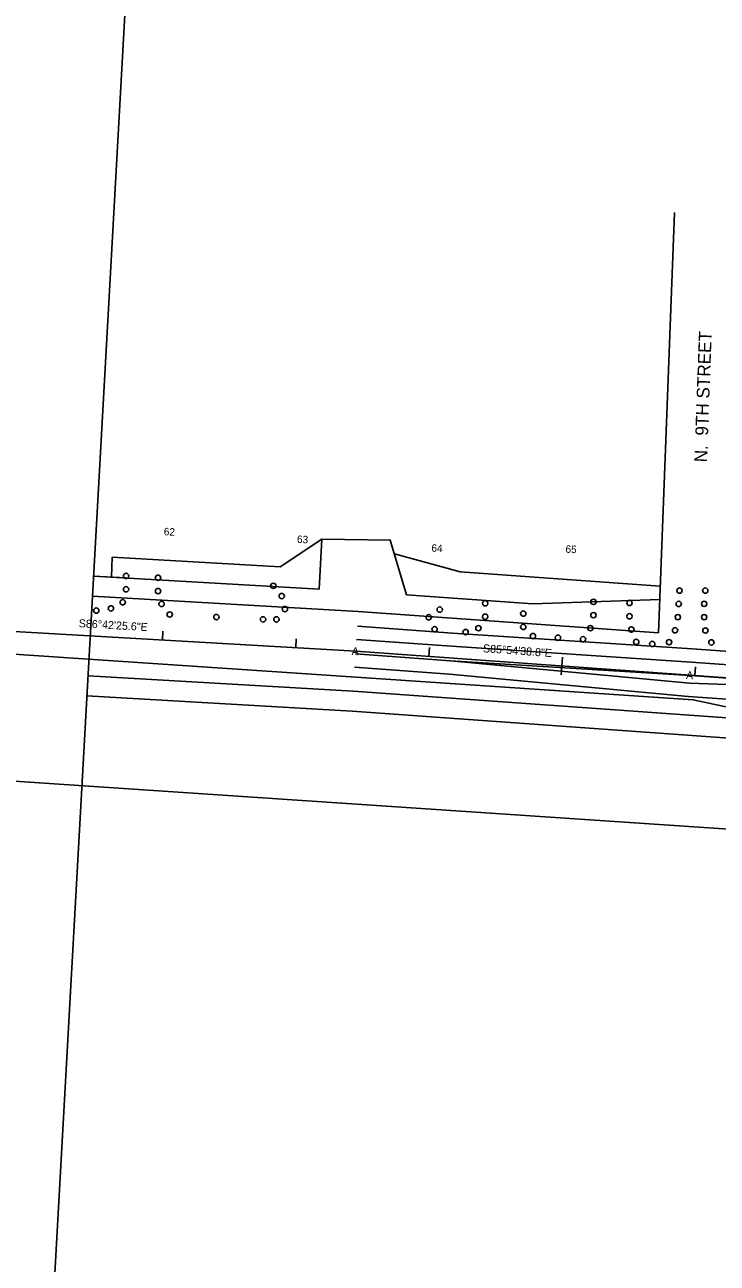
# Model space of a CAD drawing. Extents: x 679444 to 687671, y 733868 to 736107.
# Drawn here: x 685370 to 685889, y 734431 to 735359 of the extents above; entities that cross this region are included whole.
import ezdxf

# ---------------------------------------------------------------- set-up
doc = ezdxf.new("R2010")
doc.units = 0
for name, color, linetype in [('$', 7, 'Continuous'), ('BASE', 7, 'Continuous'), ('border All Plan 20-40 - Level 1', 7, 'Continuous'), ('Clipping Boundary', 7, 'Continuous'), ('MOT Stage 1', 7, 'Continuous'), ('MOT Stage 1 Lanes', 7, 'Continuous'), ('R_Horz Alg', 7, 'Continuous'), ('R_Horz Alg Station', 7, 'Continuous'), ('R_TYPE_A_CURB', 7, 'Continuous'), ('RW-EX', 7, 'Continuous'), ('RW-PR', 7, 'Continuous')]:
    doc.layers.add(name, color=color, linetype=linetype)

# ---------------------------------------------------------------- blocks, each defined once
blk = doc.blocks.new('BAREL_1772')
at = {"layer": 'MOT Stage 1'}
blk.add_circle((0, 0), 2.88, dxfattribs=at)
blk = doc.blocks.new('BAREL_1773')
at = {"layer": 'MOT Stage 1'}
blk.add_circle((0, 0), 2.88, dxfattribs=at)
blk = doc.blocks.new('BAREL_1774')
at = {"layer": 'MOT Stage 1'}
blk.add_circle((0, 0), 2.88, dxfattribs=at)
blk = doc.blocks.new('BAREL_1775')
at = {"layer": 'MOT Stage 1'}
blk.add_circle((0, 0), 2.88, dxfattribs=at)
blk = doc.blocks.new('BAREL_1776')
at = {"layer": 'MOT Stage 1'}
blk.add_circle((0, 0), 2.88, dxfattribs=at)
blk = doc.blocks.new('BAREL_1777')
at = {"layer": 'MOT Stage 1'}
blk.add_circle((0, 0), 2.88, dxfattribs=at)
blk = doc.blocks.new('BAREL_1778')
at = {"layer": 'MOT Stage 1'}
blk.add_circle((0, 0), 2.88, dxfattribs=at)
blk = doc.blocks.new('BAREL_1779')
at = {"layer": 'MOT Stage 1'}
blk.add_circle((0, 0), 2.88, dxfattribs=at)
blk = doc.blocks.new('BAREL_1790')
at = {"layer": 'MOT Stage 1'}
blk.add_circle((0, 0), 2.88, dxfattribs=at)
blk = doc.blocks.new('BAREL_1791')
at = {"layer": 'MOT Stage 1'}
blk.add_circle((0, 0), 2.88, dxfattribs=at)
blk = doc.blocks.new('BAREL_1792')
at = {"layer": 'MOT Stage 1'}
blk.add_circle((0, 0), 2.88, dxfattribs=at)
blk = doc.blocks.new('BAREL_1793')
at = {"layer": 'MOT Stage 1'}
blk.add_circle((0, 0), 2.88, dxfattribs=at)
blk = doc.blocks.new('BAREL_1794')
at = {"layer": 'MOT Stage 1'}
blk.add_circle((0, 0), 2.88, dxfattribs=at)
blk = doc.blocks.new('BAREL_1795')
at = {"layer": 'MOT Stage 1'}
blk.add_circle((0, 0), 2.88, dxfattribs=at)
blk = doc.blocks.new('BAREL_1807')
at = {"layer": 'MOT Stage 1'}
blk.add_circle((0, 0), 2.88, dxfattribs=at)
blk = doc.blocks.new('BAREL_1808')
at = {"layer": 'MOT Stage 1'}
blk.add_circle((0, 0), 2.88, dxfattribs=at)
blk = doc.blocks.new('BAREL_1809')
at = {"layer": 'MOT Stage 1'}
blk.add_circle((0, 0), 2.88, dxfattribs=at)
blk = doc.blocks.new('BAREL_1810')
at = {"layer": 'MOT Stage 1'}
blk.add_circle((0, 0), 2.88, dxfattribs=at)
blk = doc.blocks.new('BAREL_1811')
at = {"layer": 'MOT Stage 1'}
blk.add_circle((0, 0), 2.88, dxfattribs=at)
blk = doc.blocks.new('BAREL_1812')
at = {"layer": 'MOT Stage 1'}
blk.add_circle((0, 0), 2.88, dxfattribs=at)
blk = doc.blocks.new('BAREL_1813')
at = {"layer": 'MOT Stage 1'}
blk.add_circle((0, 0), 2.88, dxfattribs=at)
blk = doc.blocks.new('BAREL_1814')
at = {"layer": 'MOT Stage 1'}
blk.add_circle((0, 0), 2.88, dxfattribs=at)
blk = doc.blocks.new('BAREL_1815')
at = {"layer": 'MOT Stage 1'}
blk.add_circle((0, 0), 2.88, dxfattribs=at)
blk = doc.blocks.new('BAREL_1816')
at = {"layer": 'MOT Stage 1'}
blk.add_circle((0, 0), 2.88, dxfattribs=at)
blk = doc.blocks.new('BAREL_1817')
at = {"layer": 'MOT Stage 1'}
blk.add_circle((0, 0), 2.88, dxfattribs=at)
blk = doc.blocks.new('BAREL_1818')
at = {"layer": 'MOT Stage 1'}
blk.add_circle((0, 0), 2.88, dxfattribs=at)
blk = doc.blocks.new('BAREL_1893')
at = {"layer": 'MOT Stage 1'}
blk.add_circle((0, 0), 2.88, dxfattribs=at)
blk = doc.blocks.new('BAREL_1894')
at = {"layer": 'MOT Stage 1'}
blk.add_circle((0, 0), 2.88, dxfattribs=at)
blk = doc.blocks.new('BAREL_1895')
at = {"layer": 'MOT Stage 1'}
blk.add_circle((0, 0), 2.88, dxfattribs=at)
blk = doc.blocks.new('BAREL_1896')
at = {"layer": 'MOT Stage 1'}
blk.add_circle((0, 0), 2.88, dxfattribs=at)
blk = doc.blocks.new('BAREL_1897')
at = {"layer": 'MOT Stage 1'}
blk.add_circle((0, 0), 2.88, dxfattribs=at)
blk = doc.blocks.new('BAREL_1898')
at = {"layer": 'MOT Stage 1'}
blk.add_circle((0, 0), 2.88, dxfattribs=at)
blk = doc.blocks.new('BAREL_1899')
at = {"layer": 'MOT Stage 1'}
blk.add_circle((0, 0), 2.88, dxfattribs=at)
blk = doc.blocks.new('BAREL_1900')
at = {"layer": 'MOT Stage 1'}
blk.add_circle((0, 0), 2.88, dxfattribs=at)
blk = doc.blocks.new('BAREL_1901')
at = {"layer": 'MOT Stage 1'}
blk.add_circle((0, 0), 2.88, dxfattribs=at)
blk = doc.blocks.new('BAREL_1902')
at = {"layer": 'MOT Stage 1'}
blk.add_circle((0, 0), 2.88, dxfattribs=at)
blk = doc.blocks.new('BAREL_1903')
at = {"layer": 'MOT Stage 1'}
blk.add_circle((0, 0), 2.88, dxfattribs=at)
blk = doc.blocks.new('BAREL_1904')
at = {"layer": 'MOT Stage 1'}
blk.add_circle((0, 0), 2.88, dxfattribs=at)
blk = doc.blocks.new('BAREL_1905')
at = {"layer": 'MOT Stage 1'}
blk.add_circle((0, 0), 2.88, dxfattribs=at)
blk = doc.blocks.new('BAREL_1906')
at = {"layer": 'MOT Stage 1'}
blk.add_circle((0, 0), 2.88, dxfattribs=at)
blk = doc.blocks.new('BAREL_1907')
at = {"layer": 'MOT Stage 1'}
blk.add_circle((0, 0), 2.88, dxfattribs=at)
blk = doc.blocks.new('BAREL_1908')
at = {"layer": 'MOT Stage 1'}
blk.add_circle((0, 0), 2.88, dxfattribs=at)
blk = doc.blocks.new('BAREL_1909')
at = {"layer": 'MOT Stage 1'}
blk.add_circle((0, 0), 2.88, dxfattribs=at)
blk = doc.blocks.new('BAREL_1910')
at = {"layer": 'MOT Stage 1'}
blk.add_circle((0, 0), 2.88, dxfattribs=at)
blk = doc.blocks.new('BAREL_1915')
at = {"layer": 'MOT Stage 1'}
blk.add_circle((0, 0), 2.88, dxfattribs=at)

msp = doc.modelspace()

# ---------------------------------------------------------------- linework, layer by layer
at = {"layer": 'border All Plan 20-40 - Level 1'}
msp.add_line((685389.99, 734377.63), (685446.82, 735403.36), dxfattribs=at)
at = {"layer": 'Clipping Boundary'}
msp.add_lwpolyline([(685004.96, 734911.26), (685870.83, 734853.15), (685958.87, 734834.19), (686124.37, 734817.12), (686182.42, 734811.14), (686223.62, 734765.98), (686227.86, 734744.58), (686187.41, 734736.57), (684968, 734818.52)], close=True, dxfattribs=at)
at = {"layer": 'MOT Stage 1 Lanes'}
for p, q in [((685619.21, 734908.22), (685690.35, 734903.13)), ((685690.35, 734903.13), (685869.96, 734891.29)), ((685618.5, 734898.24), (685689.63, 734893.16)), ((685689.63, 734893.16), (685869.25, 734881.32)), ((685617.72, 734887.42), (685688.86, 734882.34)), ((685617.01, 734877.45), (685688.15, 734872.36)), ((685688.86, 734882.34), (685868.12, 734865.51)), ((685688.86, 734882.34), (685868.53, 734871.34)), ((685688.15, 734872.36), (685867.18, 734855.56)), ((685868.12, 734865.51), (686042.67, 734858.89)), ((685867.4, 734855.54), (685951.66, 734849.51))]:
    msp.add_line(p, q, dxfattribs=at)
for points in [[(685869.96, 734891.29), (686151.25, 734871.18)], [(685869.25, 734881.32), (686150.53, 734861.21)], [(685868.53, 734871.34), (686150.82, 734851.16)]]:
    msp.add_lwpolyline(points, dxfattribs=at)
at = {"layer": 'R_Horz Alg Station'}
for p, q in [((685263.44, 734909.81), (685617.87, 734889.42)), ((685617.87, 734889.42), (685868.54, 734871.5)), ((685868.54, 734871.5), (686149.79, 734851.39))]:
    msp.add_line(p, q, dxfattribs=at)
for points in [[(685473.45, 734904.41), (685473.06, 734897.75)], [(685573.28, 734898.66), (685572.9, 734892.01)], [(685673.16, 734892.15), (685672.68, 734885.5)], [(685772.9, 734885.02), (685771.95, 734871.72)], [(685872.65, 734877.89), (685872.17, 734871.24)]]:
    msp.add_lwpolyline(points, dxfattribs=at)
at = {"layer": 'R_TYPE_A_CURB'}
msp.add_line((685421.47, 734945.79), (685445.7, 734944.4), dxfattribs=at)
at = {"layer": 'RW-EX'}
for p, q in [((685844.75, 734903.27), (685856.91, 735218.44)), ((685619.8, 734919.36), (685420.64, 734930.82)), ((685619.8, 734919.36), (685844.75, 734903.27)), ((685615.93, 734859.48), (686148.06, 734821.44))]:
    msp.add_line(p, q, dxfattribs=at)
msp.add_lwpolyline([(685417.32, 734870.91), (685615.93, 734859.48)], dxfattribs=at)
at = {"layer": 'RW-PR'}
for p, q in [((685561.22, 734952.78), (685592.61, 734973.51)), ((685434.91, 734945.02), (685435.44, 734960.01)), ((685435.44, 734960.01), (685561.22, 734952.78)), ((685646.86, 734962.54), (685696.18, 734948.99)), ((685696.18, 734948.99), (685846.1, 734938.27)), ((685421.47, 734945.79), (685590.46, 734936.07))]:
    msp.add_line(p, q, dxfattribs=at)
for points in [[(685590.46, 734936.07), (685592.61, 734973.51), (685643.83, 734972.78), (685655.94, 734931.81)], [(685655.94, 734931.81), (685750.7, 734925.04), (685845.72, 734928.27)], [(685416.49, 734855.93), (685615.28, 734844.49), (685918.84, 734822.79), (685992.93, 734807.46), (686092.68, 734800.33), (686145.51, 734791.54), (686191.41, 734759.48), (686200.21, 734731.89), (686188.38, 734460.16), (686187.2, 734387.13), (686196.02, 734332.97)]]:
    msp.add_lwpolyline(points, dxfattribs=at)

# ---------------------------------------------------------------- block references
at = {"layer": 'MOT Stage 1', "xscale": 0.6945420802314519, "yscale": 0.6945420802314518, "rotation": 87.04179557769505}
for name, p in [('BAREL_1772', (685445.79, 734945.89)), ('BAREL_1773', (685469.75, 734944.53)), ('BAREL_1899', (685556.08, 734938.52)), ('BAREL_1774', (685445.79, 734935.89)), ('BAREL_1775', (685469.75, 734934.53)), ('BAREL_1898', (685562.44, 734930.8)), ('BAREL_1790', (685860.58, 734934.94)), ('BAREL_1793', (685879.92, 734934.94)), ('BAREL_1807', (685423.42, 734919.94)), ('BAREL_1809', (685434.45, 734921.57)), ('BAREL_1808', (685443.31, 734926.2)), ('BAREL_1810', (685472.38, 734924.88)), ('BAREL_1897', (685564.8, 734921.09)), ('BAREL_1909', (685680.82, 734920.64)), ('BAREL_1903', (685714.89, 734925.38)), ('BAREL_1776', (685796.07, 734926.49)), ('BAREL_1777', (685823.09, 734925.66)), ('BAREL_1791', (685859.97, 734924.96)), ('BAREL_1794', (685879.03, 734924.98)), ('BAREL_1893', (685478.52, 734916.99)), ('BAREL_1894', (685513.47, 734915.11)), ('BAREL_1895', (685548.43, 734913.38)), ('BAREL_1896', (685558.43, 734913.38)), ('BAREL_1908', (685672.6, 734914.94)), ('BAREL_1904', (685714.89, 734915.38)), ('BAREL_1902', (685743.45, 734917.7)), ('BAREL_1778', (685796.07, 734916.49)), ('BAREL_1779', (685823.09, 734915.66)), ('BAREL_1792', (685859.32, 734914.98)), ('BAREL_1795', (685879.03, 734914.98)), ('BAREL_1907', (685677.03, 734905.97)), ('BAREL_1906', (685700.29, 734903.84)), ('BAREL_1905', (685709.87, 734906.73)), ('BAREL_1901', (685743.45, 734907.7)), ('BAREL_1900', (685750.72, 734900.84)), ('BAREL_1811', (685793.78, 734906.75)), ('BAREL_1813', (685824.49, 734905.76)), ('BAREL_1815', (685857.25, 734905.2)), ('BAREL_1817', (685880, 734905.03)), ('BAREL_1915', (685769.49, 734899.63)), ('BAREL_1812', (685788.26, 734898.42)), ('BAREL_1814', (685828.12, 734896.44)), ('BAREL_1910', (685840.16, 734894.9)), ('BAREL_1816', (685852.76, 734896.26)), ('BAREL_1818', (685884.44, 734896.06))]:
    msp.add_blockref(name, p, dxfattribs=at)

# ---------------------------------------------------------------- texts
at = {"layer": '$'}
for s, p in [('62', (685473.95, 734976.47)), ('63', (685573.78, 734970.73)), ('64', (685674.53, 734964.16)), ('65', (685775.02, 734963.34))]:
    msp.add_text(s, height=5.6, rotation=357.04154, dxfattribs=at).set_placement(p)
at = {"layer": 'BASE'}
msp.add_text('N.  9TH STREET', height=9.6, rotation=87.90993, dxfattribs=at).set_placement((685881.2, 735030.99))
at = {"layer": 'R_Horz Alg'}
for rotation, p in [(356.30893, (685614.68, 734886.62)), (355.91076, (685865.34, 734868.72))]:
    msp.add_text('A', height=6, rotation=rotation, dxfattribs=at).set_placement(p)
at = {"layer": 'R_Horz Alg Station'}
for s, rotation, p in [('S86%%d42\'25.6"E', 356.70711, (685410.15, 734907.5)), ('S85%%d54\'38.8"E', 355.91076, (685713.09, 734888.75))]:
    msp.add_text(s, height=6, rotation=rotation, dxfattribs=at).set_placement(p)

doc.saveas('drawing.dxf')
